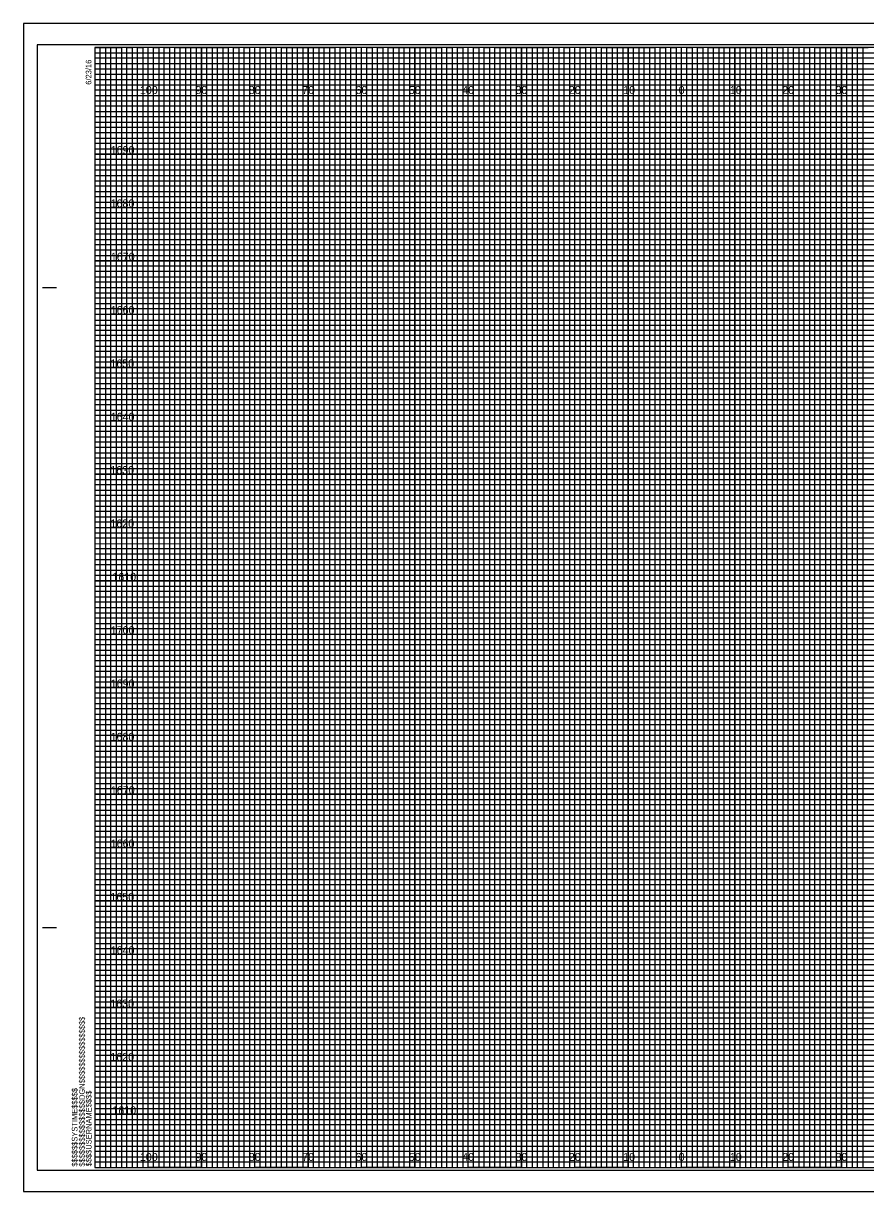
# Model space of a CAD drawing. Extents: x -13 to 323, y -5 to 6154.
# Drawn here: x -13.4 to 144.5, y 3955.5 to 4174.5 of the extents above; entities that cross this region are included whole.
import ezdxf

# ---------------------------------------------------------------- set-up
doc = ezdxf.new("R2010")
doc.units = 0
for name, color, linetype in [('Prop Retaining Wall', 7, 'Continuous'), ('Prop XS Alignment Label', 7, 'Continuous'), ('Prop XS DDE', 7, 'Continuous'), ('Prop XS DDE Elevations', 7, 'Continuous'), ('Prop XS DDE Slope Text', 7, 'Continuous'), ('Prop XS Earthwork Shape', 7, 'Continuous'), ('Prop XS Elevation Labels', 7, 'Continuous'), ('Prop XS Station Labels', 7, 'Continuous'), ('Raster_Level_0', 7, 'Continuous'), ('Scratch_Level_3', 7, 'Continuous'), ('Sheet Cutting Line CELL', 7, 'Continuous')]:
    doc.layers.add(name, color=color, linetype=linetype)

msp = doc.modelspace()

# ---------------------------------------------------------------- linework, layer by layer
at = {"layer": 'Prop Retaining Wall'}
for p, q in [((0, 4169), (260, 4169)), ((260, 4167.98), (0, 4167.98)), ((0, 4167.98), (0, 4167)), ((0, 4167), (260, 4167)), ((260, 4165.89), (0, 4165.89)), ((0, 4165.89), (0, 4164)), ((0, 4164), (320, 4164))]:
    msp.add_line(p, q, dxfattribs=at)
for points in [[(0, 4163), (270, 4163), (320, 4163), (320, 4162), (0, 4162)], [(0, 4161), (320, 4161), (320, 4159), (0, 4159)], [(0, 4158), (320, 4158), (320, 4157), (0, 4156.98)], [(0, 4156), (320, 4156), (320, 4154), (0, 4154)], [(0, 4153), (320, 4153), (320, 4152), (0, 4152)], [(0, 4151), (320, 4151), (320, 4149), (0, 4149)], [(0, 4148), (320, 4148), (320, 4147), (0, 4147)], [(0, 4146), (320, 4146), (320, 4144), (0, 4144)], [(0, 4143), (320, 4143), (320, 4142), (0, 4142)], [(0, 4141), (320, 4141), (320, 4139), (0, 4139)], [(0, 4138), (320, 4138), (320, 4137), (0, 4137)], [(0, 4136), (320, 4136), (320, 4133.95), (320, 4133), (320, 4132), (0, 4132)], [(0, 4134), (320, 4134), (320, 4133), (0, 4133)], [(0, 4131), (320, 4131), (320, 4129), (0, 4129.03)], [(0, 4129.03), (320, 4129), (320, 4128), (0, 4128)], [(0, 4127), (320, 4127), (320, 4126), (0, 4126)], [(0, 4124), (320, 4124), (320, 4123), (0, 4123)], [(0, 4122), (320, 4122), (320, 4121), (0, 4121)], [(-0.07, 4118.89), (320, 4118.89), (320, 4117.88), (-0.07, 4117.88)], [(0, 4117), (320, 4117), (320, 4116), (0, 4116)], [(0, 4114), (320, 4114), (320, 4113), (0, 4113)], [(0, 4112), (320, 4112), (320, 4111), (0, 4111)], [(0, 4109), (320, 4109), (320, 4108), (0, 4108)], [(0, 4107), (320, 4107), (320, 4106), (0, 4106)], [(0, 4104), (320, 4104), (320, 4103), (0, 4103)], [(0, 4102), (320, 4102), (320, 4101), (0, 4101)], [(0, 4099), (320, 4099), (319.99, 4097.98), (0, 4098)], [(0, 4097), (320, 4097), (320, 4096), (0, 4096)], [(0, 4094), (320, 4094), (320, 4093), (0, 4093)], [(0, 4092), (320, 4092), (320, 4091), (0, 4091)], [(0, 4089), (320, 4089), (320, 4088), (0, 4088)], [(0, 4087), (320, 4087), (320, 4086), (0, 4086)], [(0, 4084), (320, 4084), (320, 4083), (0, 4083)], [(0, 4082), (320, 4082), (320, 4081), (0, 4081)], [(0, 4079), (320, 4079), (320, 4078), (0, 4078)], [(0, 4076.99), (320.07, 4076.91), (320, 4076), (0, 4076)], [(0, 4074), (320, 4074), (320, 4073), (0, 4073)], [(0, 4072), (320, 4072), (320, 4071), (0, 4071)], [(0, 4069), (320, 4069), (320, 4068), (0, 4068)], [(0, 4067), (320, 4067), (320, 4066), (0, 4066)], [(0, 4064), (320, 4064), (320, 4063), (0, 4063)], [(0, 4062), (320, 4062), (320, 4061), (0, 4061)], [(0, 4059), (320, 4059), (320, 4058), (0, 4058)], [(0, 4057), (320, 4057), (320, 4056), (0, 4056)], [(0, 4054), (320, 4054), (320, 4053), (0, 4053)], [(0, 4052), (320, 4052), (320, 4051), (0, 4051)], [(0, 4049), (320, 4049), (320, 4048), (0, 4048)], [(0, 4047), (320, 4047), (320, 4046), (0, 4046)], [(0, 4044), (320, 4044), (320, 4043), (0, 4043)], [(0, 4042), (320, 4042), (320, 4041), (0, 4041)], [(0, 4039), (320, 4039), (319.99, 4037.98), (0, 4038)], [(0, 4037), (320, 4037), (320, 4036), (0, 4036)], [(0, 4034), (320, 4034), (320, 4033), (0, 4033)], [(0, 4032), (320, 4032), (320, 4031), (0, 4031)], [(0, 4029), (320, 4029), (320, 4028), (0, 4028)], [(0, 4027), (320, 4027), (320, 4026), (0, 4026)], [(0, 4024), (320, 4024), (320, 4023), (0, 4023)], [(0, 4022), (320, 4022), (320, 4021), (0, 4021)], [(0, 4019), (320, 4019), (320, 4018), (0, 4018)], [(0, 4016.99), (320.07, 4016.91), (320, 4016), (0, 4016)], [(0, 4014), (320, 4014), (320, 4013), (0, 4013)], [(0, 4012), (320, 4012), (320, 4011), (0, 4011)], [(0, 4009), (320, 4009), (320, 4008), (0, 4008)], [(0, 4007), (320, 4007), (320, 4006), (0, 4006)], [(0, 4004), (320, 4004), (320, 4003), (0, 4003)], [(0, 4002), (320, 4002), (320, 4001), (0, 4001)], [(0, 3999), (320, 3999), (320, 3998), (0, 3998)], [(0, 3997), (320, 3997), (320, 3996), (0, 3996)], [(0, 3994), (320, 3994), (320, 3993), (0, 3993)], [(0, 3992), (320, 3992), (320, 3991), (0, 3991)], [(0, 3989), (320, 3989), (320, 3988), (0, 3988)], [(0, 3987), (320, 3987), (320, 3986), (0, 3986)], [(0, 3984), (320, 3984), (320, 3983), (0, 3983)], [(0, 3982), (320, 3982), (320, 3981), (0, 3981)], [(0, 3979), (320, 3979), (320, 3978), (0, 3978)], [(0, 3977), (320, 3977), (320, 3976), (0, 3976)], [(0, 3974), (320, 3974), (320, 3973), (0, 3973)], [(0, 3972), (320, 3972), (320, 3971), (0, 3971)], [(0, 3969), (320, 3969), (320, 3968), (0, 3968)], [(0, 3967), (320, 3967), (320, 3966), (0, 3966)], [(0, 3964), (320, 3964), (320, 3963), (0, 3963)], [(0, 3962), (320, 3962), (320, 3961), (0, 3961)]]:
    msp.add_lwpolyline(points, dxfattribs=at)
at = {"layer": 'Prop XS Alignment Label'}
for p, q in [((-9.8, 4125), (-7.3, 4125)), ((-9.7, 4125), (-7.2, 4125)), ((-9.8, 4005), (-7.3, 4005)), ((-9.7, 4005), (-7.2, 4005)), ((0, 3960), (0, 3960)), ((0, 3960), (0, 3960)), ((0, 3960), (0, 3960)), ((0, 3960), (0, 3960)), ((0, 3960), (0, 3960)), ((0, 3960), (0, 3960)), ((0, 3960), (0, 3960))]:
    msp.add_line(p, q, dxfattribs=at)
msp.add_lwpolyline([(320, 4170), (0, 4170), (0, 3960), (320, 3960)], close=True, dxfattribs=at)
at = {"layer": 'Prop XS DDE'}
msp.add_lwpolyline([(-13.4, 3955.5), (323.3, 3955.5), (323.3, 4174.5), (-13.4, 4174.5)], close=True, dxfattribs=at)
at = {"layer": 'Prop XS DDE Elevations'}
for p, q in [((10, 3960), (10, 4170)), ((20, 3960), (20, 4170)), ((30, 3960), (30, 4170)), ((40, 3960), (40, 4170)), ((50, 3960), (50, 4170)), ((60, 3960), (60, 4170)), ((70, 3960), (70, 4170)), ((80, 3960), (80, 4170)), ((90, 3960), (90, 4170)), ((100, 3960), (100, 4170)), ((110, 3960), (110, 4170)), ((120, 3960), (120, 4170)), ((130, 3960), (130, 4170)), ((140, 3960), (140, 4170)), ((0, 4160), (320, 4160)), ((0, 4150), (320, 4150)), ((0, 4140), (320, 4140)), ((0, 4130), (320, 4130)), ((0, 4120), (320, 4120)), ((0, 4110), (320, 4110)), ((0, 4100), (320, 4100)), ((0, 4090), (320, 4090)), ((0, 4080), (320, 4080)), ((0, 4070), (320, 4070)), ((0, 4060), (320, 4060)), ((0, 4050), (320, 4050)), ((0, 4040), (320, 4040)), ((0, 4030), (320, 4030)), ((0, 4020), (320, 4020)), ((0, 4010), (320, 4010)), ((0, 4000), (320, 4000)), ((0, 3990), (320, 3990)), ((0, 3980), (320, 3980)), ((0, 3970), (320, 3970))]:
    msp.add_line(p, q, dxfattribs=at)
at = {"layer": 'Prop XS DDE Slope Text'}
msp.add_lwpolyline([(-10.8, 3959.5), (322.4, 3959.5), (322.4, 4170.5), (-10.8, 4170.5)], close=True, dxfattribs=at)
at = {"layer": 'Prop XS Earthwork Shape'}
for p, q in [((10, 4170), (0, 4170)), ((10, 3960), (10, 4170)), ((30, 4170), (20, 4170)), ((20, 4170), (20, 3960)), ((30, 3960), (30, 4170)), ((50, 4170), (40, 4170)), ((40, 4170), (40, 3960)), ((50, 3960), (50, 4170)), ((70, 4170), (60, 4170)), ((60, 4170), (60, 3960)), ((70, 3960), (70, 4170)), ((90, 4170), (80, 4170)), ((80, 4170), (80, 3960)), ((90, 3960), (90, 4170)), ((110, 4170), (100, 4170)), ((100, 4170), (100, 3960)), ((110, 3960), (110, 4170)), ((130, 4170), (120, 4170)), ((120, 4170), (120, 3960)), ((130, 3960), (130, 4170)), ((150, 4170), (140, 4170)), ((140, 4170), (140, 3960)), ((20, 3960), (10, 3960)), ((40, 3960), (30, 3960)), ((60, 3960), (50, 3960)), ((80, 3960), (70, 3960)), ((100, 3960), (90, 3960)), ((120, 3960), (110, 3960)), ((140, 3960), (130, 3960))]:
    msp.add_line(p, q, dxfattribs=at)
for points in [[(0, 4160), (320, 4160), (320, 4150), (0, 4150)], [(0, 4140), (320, 4140), (320, 4130), (0, 4130)], [(0, 4120), (320, 4120), (320, 4110), (0, 4110)], [(0, 4100), (320, 4100), (320, 4090), (0, 4090)], [(0, 4080), (320, 4080), (320, 4070), (0, 4070)], [(0, 4060), (320, 4060), (320, 4050), (0, 4050)], [(0, 4040), (320, 4040), (320, 4030), (0, 4030)], [(0, 4020), (320, 4020), (320, 4010), (0, 4010)], [(0, 4000), (320, 4000), (320, 3990), (0, 3990)], [(0, 3980), (320, 3980), (320, 3970), (0, 3970)]]:
    msp.add_lwpolyline(points, dxfattribs=at)
at = {"layer": 'Prop XS Elevation Labels'}
for points in [[(0, 3960), (1, 3960), (1, 4170), (2, 4170), (2, 3960)], [(2, 3960), (3, 3960), (3, 4170), (4, 4170), (4, 3960)], [(5, 3960), (6, 3960), (6, 4170), (7, 4170), (7, 3960)], [(7, 3960), (8, 3960), (8, 4170), (9, 4170), (9, 3960)], [(10, 3960), (11, 3960), (11, 4170), (12, 4170), (12, 3960)], [(12, 3960), (13, 3960), (13, 4170), (14, 4170), (14, 3960)], [(15, 3960), (16, 3960), (16, 4170), (17, 4170), (17, 3960)], [(17, 3960), (18, 3960), (18, 4170), (19, 4170), (19, 3960)], [(20, 3960), (21, 3960), (21, 4170), (22, 4170), (22, 3960)], [(22, 3960), (23, 3960), (23, 4170), (24, 4170), (24, 3960)], [(25, 3960), (26, 3960), (26, 4170), (27, 4170), (27, 3960)], [(27, 3960), (28, 3960), (28, 4170), (29, 4170), (29, 3960)], [(30, 3960), (31, 3960), (31, 4170), (32, 4170), (32, 3960)], [(32, 3960), (33, 3960), (33, 4170), (34, 4170), (34, 3960)], [(35, 3960), (36, 3960), (36, 4170), (37, 4170), (37, 3960)], [(37, 3960), (38, 3960), (38, 4170), (39, 4170), (39, 3960)], [(40, 3960), (41, 3960), (41, 4170), (42, 4170), (42, 3960)], [(42, 3960), (43, 3960), (43, 4170), (44, 4170), (44, 3960)], [(45, 3960), (46, 3960), (46, 4170), (47, 4170), (47, 3960)], [(47, 3960), (48, 3960), (48, 4170), (49, 4170), (49, 3960)], [(50, 3960), (51, 3960), (51, 4170), (52, 4170), (52, 3960)], [(52, 3960), (53, 3960), (53, 4170), (54, 4170), (54, 3960)], [(55, 3960), (56, 3960), (56, 4170), (57, 4170), (57, 3960)], [(57, 3960), (58, 3960), (58, 4170), (59, 4170), (59, 3960)], [(60, 3960), (61, 3960), (61, 4170), (62, 4170), (62, 3960)], [(62, 3960), (63, 3960), (63, 4170), (64, 4170), (64, 3960)], [(65, 3960), (66, 3960), (66, 4170), (67, 4170), (67, 3960)], [(67, 3960), (68, 3960), (68, 4170), (69, 4170), (69, 3960)], [(70, 3960), (71, 3960), (71, 4170), (72, 4170), (72, 3960)], [(72, 3960), (73, 3960), (73, 4170), (74, 4170), (74, 3960)], [(75, 3960), (76, 3960), (76, 4170), (77, 4170), (77, 3960)], [(77, 3960), (78, 3960), (78, 4170), (79, 4170), (79, 3960)], [(80, 3960), (81, 3960), (81, 4170), (82, 4170), (82, 3960)], [(82, 3960), (83, 3960), (83, 4170), (84, 4170), (84, 3960)], [(85, 3960), (86, 3960), (86, 4170), (87, 4170), (87, 3960)], [(87, 3960), (88, 3960), (88, 4170), (89, 4170), (89, 3960)], [(90, 3960), (91, 3960), (91, 4170), (92, 4170), (92, 3960)], [(92, 3960), (93, 3960), (93, 4170), (94, 4170), (94, 3960)], [(95, 3960), (96, 3960), (96, 4170), (97, 4170), (97, 3960)], [(97, 3960), (98, 3960), (98, 4170), (99, 4170), (99, 3960)], [(100, 3960), (101, 3960), (101, 4170), (102, 4170), (102, 3960)], [(102, 3960), (103, 3960), (103, 4170), (104, 4170), (104, 3960)], [(105, 3960), (106, 3960), (106, 4170), (107, 4170), (107, 3960)], [(107, 3960), (108, 3960), (108, 4170), (109, 4170), (109, 3960)], [(110, 3960), (111, 3960), (111, 4170), (112, 4170), (112, 3960)], [(112, 3960), (113, 3960), (113, 4170), (114, 4170), (114, 3960)], [(115, 3960), (116, 3960), (116, 4170), (117, 4170), (117, 3960)], [(117, 3960), (118, 3960), (118, 4170), (119, 4170), (119, 3960)], [(120, 3960), (121, 3960), (121, 4170), (122, 4170), (122, 3960)], [(122, 3960), (123, 3960), (123, 4170), (124, 4170), (124, 3960)], [(125, 3960), (126, 3960), (126, 4170), (127, 4170), (127, 3960)], [(127, 3960), (128, 3960), (128, 4170), (129, 4170), (129, 3960)], [(130, 3960), (131, 3960), (131, 4170), (132, 4170), (132, 3960)], [(132, 3960), (133, 3960), (133, 4170), (134, 4170), (134, 3960)], [(135, 3960), (136, 3960), (136, 4170), (137, 4170), (137, 3960)], [(137, 3960), (138, 3960), (138, 4170), (139, 4170), (139, 3960)], [(140, 3960), (141, 3960), (141, 4170), (142, 4170), (142, 3960)], [(142, 3960), (143, 3960), (143, 4170), (144, 4170), (144, 3960)]]:
    msp.add_lwpolyline(points, dxfattribs=at)
at = {"layer": 'Prop XS Station Labels'}
for points in [[(0, 4170), (5, 4170), (5, 3960), (15, 3960), (15, 4170), (25, 4170), (25, 3960), (35, 3960), (35, 4170), (45, 4170), (45, 3960), (55, 3960), (55, 4170), (65, 4170), (65, 3960), (75, 3960), (75, 4170), (85, 4170), (85, 3960), (95, 3960), (95, 4170), (105, 4170), (105, 3960), (115, 3960), (115, 4170), (125, 4170), (125, 3960), (135, 3960), (135, 4170), (145, 4170)], [(0, 4165), (275, 4165)], [(0, 4145), (320, 4145), (320, 4155), (0, 4155)], [(0, 4125), (320, 4125), (320, 4135), (0, 4135)], [(0, 4105), (320, 4105), (320, 4115), (0, 4115)], [(0, 4085), (320, 4085), (320, 4095), (0, 4095)], [(0, 4065), (320, 4065), (320, 4075), (0, 4075)], [(0, 4045), (320, 4045), (320, 4055), (0, 4055)], [(0, 4025), (320, 4025), (320, 4035), (0, 4035)], [(0, 4005), (320, 4005), (320, 4015), (0, 4015)], [(0, 3985), (320, 3985), (320, 3995), (0, 3995)], [(0, 3965), (320, 3965), (320, 3975), (0, 3975)]]:
    msp.add_lwpolyline(points, dxfattribs=at)
at = {"layer": 'Sheet Cutting Line CELL'}
for p, q in [((323.3, 4174.5), (-13.4, 4174.5)), ((-13.4, 4174.5), (-13.4, 3955.5)), ((-13.4, 3955.5), (323.3, 3955.5))]:
    msp.add_line(p, q, dxfattribs=at)

# ---------------------------------------------------------------- texts
at = {"layer": 'Prop XS Alignment Label'}
for s, p in [('6/23/16', (-0.65, 4163)), ('$$$$$$$$$$$$$$$$DGN$$$$$$$$$$$$$$$$', (-1.88, 3960.18)), ('$$$$$$SYSTIME$$$$$', (-3.26, 3960.18)), ('$$$$USERNAME$$$$', (-0.62, 3960.23))]:
    msp.add_text(s, height=1.05, rotation=90, dxfattribs=at).set_placement(p)
at = {"layer": 'Raster_Level_0'}
for s, p in [('100', (8.44, 4161.25)), ('90', (18.86, 4161.25)), ('80', (28.86, 4161.25)), ('70', (38.86, 4161.25)), ('60', (48.86, 4161.25)), ('50', (58.86, 4161.25)), ('40', (68.86, 4161.25)), ('30', (78.86, 4161.25)), ('20', (88.86, 4161.25)), ('10', (99.04, 4161.25)), ('0', (109.45, 4161.25)), ('0', (109.45, 4161.25)), ('10', (119.04, 4161.25)), ('20', (128.86, 4161.25)), ('30', (138.86, 4161.25)), ('100', (8.44, 3961.25)), ('90', (18.86, 3961.25)), ('80', (28.86, 3961.25)), ('70', (38.86, 3961.25)), ('60', (48.86, 3961.25)), ('50', (58.86, 3961.25)), ('40', (68.86, 3961.25)), ('30', (78.86, 3961.25)), ('20', (88.86, 3961.25)), ('10', (99.04, 3961.25)), ('0', (109.45, 3961.25)), ('0', (109.45, 3961.25)), ('10', (119.04, 3961.25)), ('20', (128.86, 3961.25)), ('30', (138.86, 3961.25))]:
    msp.add_text(s, height=1.5, dxfattribs=at).set_placement(p)
at = {"layer": 'Scratch_Level_3'}
for s, p in [('1690', (2.97, 4150)), ('1680', (2.95, 4140)), ('1670', (3, 4130)), ('1660', (2.97, 4120)), ('1650', (2.92, 4110)), ('1640', (2.97, 4100)), ('1630', (2.89, 4090)), ('1620', (2.9, 4080)), ('1610', (3.28, 4070)), ('1700', (2.98, 4060)), ('1690', (2.97, 4050)), ('1680', (2.95, 4040)), ('1670', (3, 4030)), ('1660', (2.97, 4020)), ('1650', (2.92, 4010)), ('1640', (2.97, 4000)), ('1630', (2.89, 3990)), ('1620', (2.9, 3980)), ('1610', (3.28, 3970))]:
    msp.add_text(s, height=1.5, dxfattribs=at).set_placement(p)

doc.saveas('drawing.dxf')
